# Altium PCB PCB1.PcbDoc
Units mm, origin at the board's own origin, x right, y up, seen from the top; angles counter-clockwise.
Board outline 152.4 x 101.6 mm, 2 copper layers (Top Layer, Bottom Layer); 138 components, 71 nets, 353 pads, 0 vias.
Unrouted connection lines stored in the file: 264.
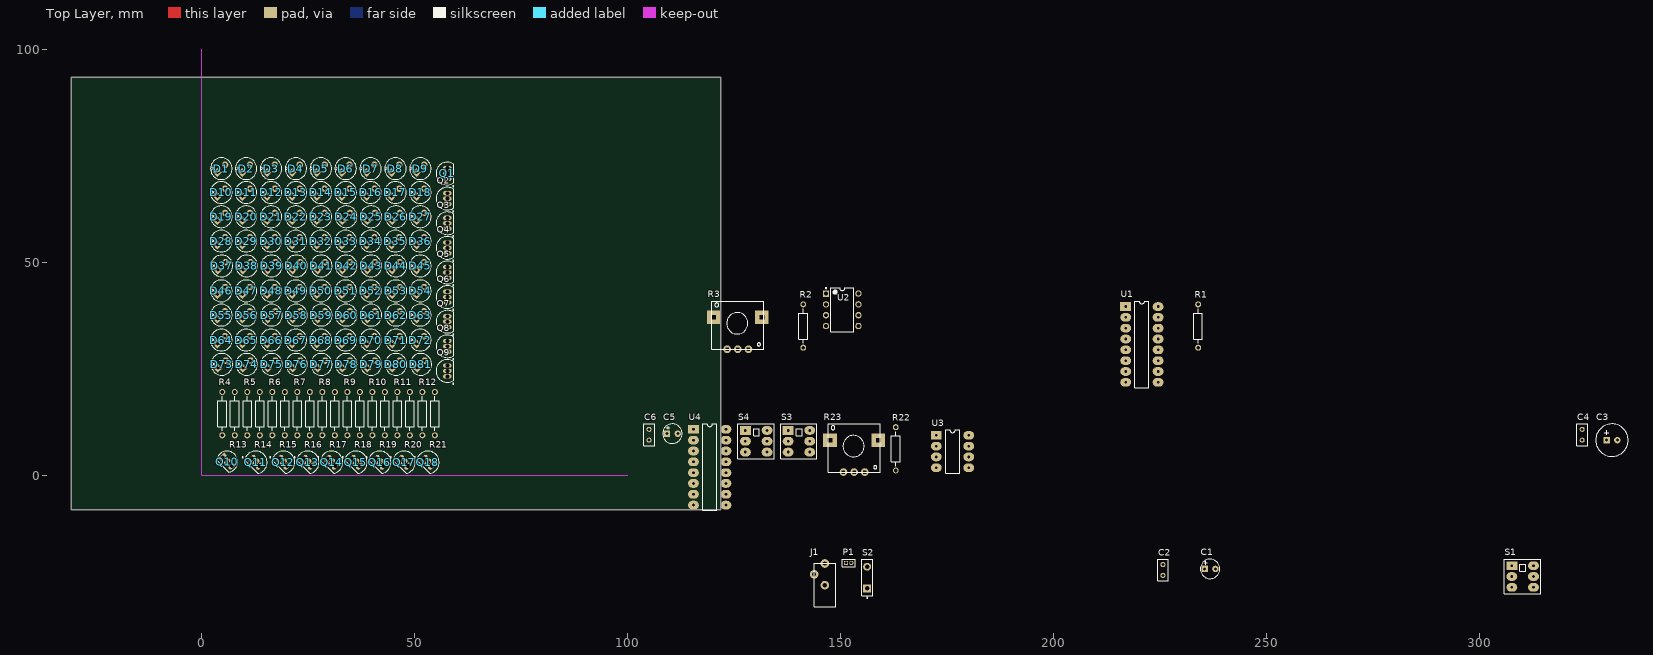
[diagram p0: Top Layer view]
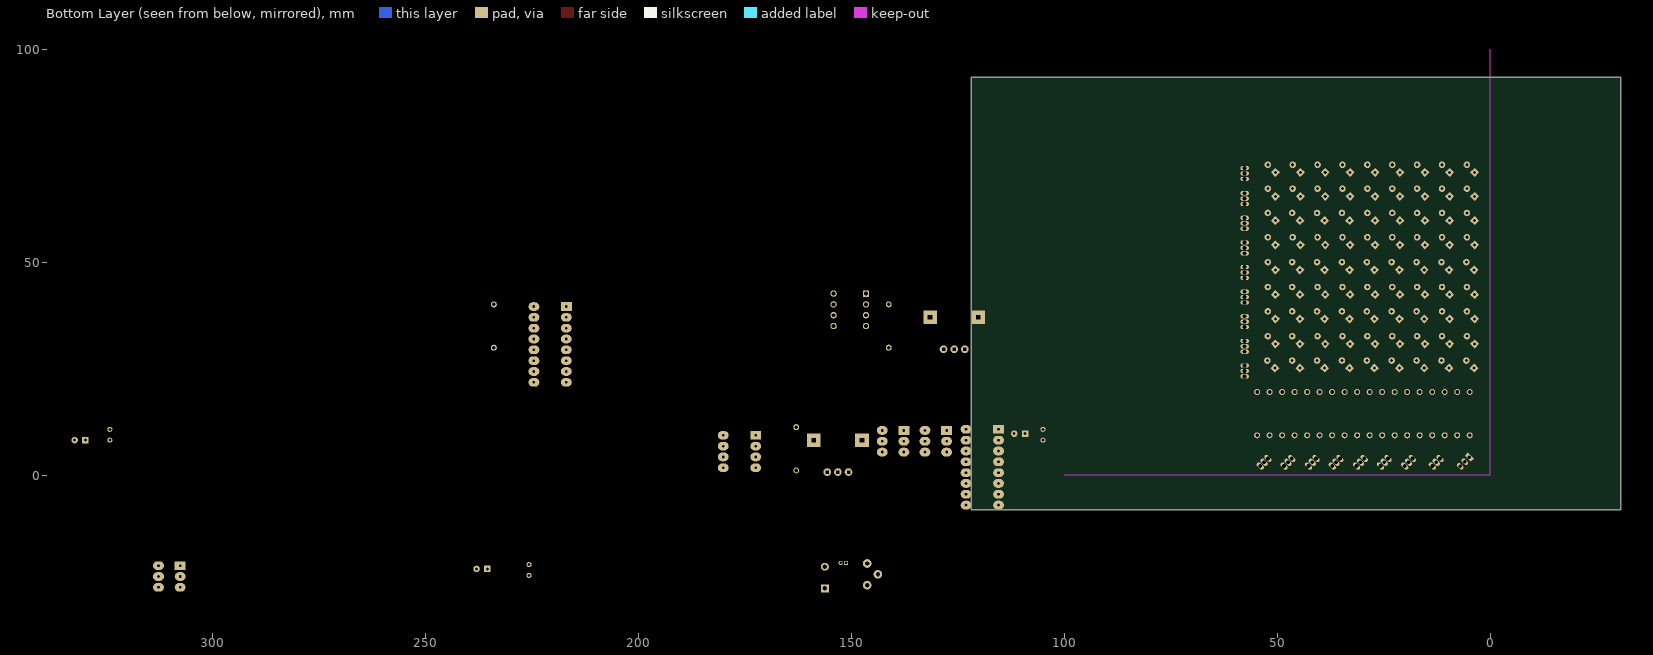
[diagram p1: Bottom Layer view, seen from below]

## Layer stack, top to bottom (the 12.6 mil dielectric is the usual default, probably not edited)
Top Solder: solder mask 0.0102, Solder Resist, Dk 3.5
Top Layer: signal copper 0.0356
Dielectric 1: dielectric 0.32, FR-4, Dk 4.8
Bottom Layer: signal copper 0.0356
Bottom Solder: solder mask 0.0102, Solder Resist, Dk 3.5

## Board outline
-30.607,-8.128 121.793,-8.128 121.793,93.472 -30.607,93.472

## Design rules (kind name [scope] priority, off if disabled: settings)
Clearance [All] p1: gap=0.254
PolygonConnect [All] p1: connectstyle=Relief reliefconductorwidth=0.254 reliefentries=4 polygonreliefangle="90 Angle" airgapwidth=0.254
RoutingVias [All] p1: holewidth=0.711 width=1.27 viastyle="Through Hole" minholewidth=0.711 minwidth=1.27 maxholewidth=0.711 maxwidth=1.27
SolderMaskExpansion [All] p1: expansion=0.102
Width [All] p1: maxlimit=0.254 minlimit=0.254 preferedwidth=0.254
30 further rules are at their usual default settings.

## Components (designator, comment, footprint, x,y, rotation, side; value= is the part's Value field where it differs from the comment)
C1 "Cap Pol2" 1UF电容器 235.458,-21.971 r0 top
C2 "Cap" RAD-0.1 225.679,-22.225 r90 top
C3 "Cap Pol2" 220UF电容 329.819,8.255 r0 top
C4 "Cap" RAD-0.1 324.104,9.525 r90 top
C5 "Cap Pol2" 1UF电容器 109.22,9.779 r0 top
C6 "Cap" RAD-0.1 105.029,9.525 r90 top
D1 "LED1" 发光二极管 3.683,71.12 r45 top
D2 "LED1" 发光二极管 9.525,71.12 r45 top
D3 "LED1" 发光二极管 15.367,71.12 r45 top
D4 "LED1" 发光二极管 21.209,71.12 r45 top
D5 "LED1" 发光二极管 27.051,71.12 r45 top
D6 "LED1" 发光二极管 32.893,71.12 r45 top
D7 "LED1" 发光二极管 38.735,71.12 r45 top
D8 "LED1" 发光二极管 44.577,71.12 r45 top
D9 "LED1" 发光二极管 50.419,71.12 r45 top
D10 "LED1" 发光二极管 3.683,65.514 r45 top
D11 "LED1" 发光二极管 9.525,65.514 r45 top
D12 "LED1" 发光二极管 15.367,65.514 r45 top
D13 "LED1" 发光二极管 21.209,65.514 r45 top
D14 "LED1" 发光二极管 27.051,65.514 r45 top
D15 "LED1" 发光二极管 32.893,65.514 r45 top
D16 "LED1" 发光二极管 38.735,65.514 r45 top
D17 "LED1" 发光二极管 44.577,65.514 r45 top
D18 "LED1" 发光二极管 50.419,65.514 r45 top
D19 "LED1" 发光二极管 3.683,59.817 r45 top
D20 "LED1" 发光二极管 9.525,59.817 r45 top
D21 "LED1" 发光二极管 15.367,59.817 r45 top
D22 "LED1" 发光二极管 21.209,59.817 r45 top
D23 "LED1" 发光二极管 27.051,59.817 r45 top
D24 "LED1" 发光二极管 33.02,59.817 r45 top
D25 "LED1" 发光二极管 38.862,59.817 r45 top
D26 "LED1" 发光二极管 44.704,59.817 r45 top
D27 "LED1" 发光二极管 50.419,59.817 r45 top
D28 "LED1" 发光二极管 3.683,54.102 r45 top
D29 "LED1" 发光二极管 9.525,54.102 r45 top
D30 "LED1" 发光二极管 15.367,54.102 r45 top
D31 "LED1" 发光二极管 21.209,54.102 r45 top
D32 "LED1" 发光二极管 27.051,54.102 r45 top
D33 "LED1" 发光二极管 32.893,54.102 r45 top
D34 "LED1" 发光二极管 38.735,54.102 r45 top
D35 "LED1" 发光二极管 44.577,54.102 r45 top
D36 "LED1" 发光二极管 50.419,54.102 r45 top
D37 "LED1" 发光二极管 3.81,48.26 r45 top
D38 "LED1" 发光二极管 9.652,48.26 r45 top
D39 "LED1" 发光二极管 15.494,48.26 r45 top
D40 "LED1" 发光二极管 21.336,48.26 r45 top
D41 "LED1" 发光二极管 27.178,48.26 r45 top
D42 "LED1" 发光二极管 33.02,48.26 r45 top
D43 "LED1" 发光二极管 38.862,48.26 r45 top
D44 "LED1" 发光二极管 44.704,48.26 r45 top
D45 "LED1" 发光二极管 50.419,48.26 r45 top
D46 "LED1" 发光二极管 3.683,42.418 r45 top
D47 "LED1" 发光二极管 9.525,42.418 r45 top
D48 "LED1" 发光二极管 15.367,42.418 r45 top
D49 "LED1" 发光二极管 21.209,42.418 r45 top
D50 "LED1" 发光二极管 27.051,42.418 r45 top
D51 "LED1" 发光二极管 32.893,42.418 r45 top
D52 "LED1" 发光二极管 38.735,42.418 r45 top
D53 "LED1" 发光二极管 44.704,42.418 r45 top
D54 "LED1" 发光二极管 50.419,42.418 r45 top
D55 "LED1" 发光二极管 3.683,36.703 r45 top
D56 "LED1" 发光二极管 9.525,36.703 r45 top
D57 "LED1" 发光二极管 15.494,36.703 r45 top
D58 "LED1" 发光二极管 21.336,36.703 r45 top
D59 "LED1" 发光二极管 27.178,36.703 r45 top
D60 "LED1" 发光二极管 33.02,36.703 r45 top
D61 "LED1" 发光二极管 38.862,36.703 r45 top
D62 "LED1" 发光二极管 44.704,36.703 r45 top
D63 "LED1" 发光二极管 50.419,36.703 r45 top
D64 "LED1" 发光二极管 3.683,30.861 r45 top
D65 "LED1" 发光二极管 9.525,30.861 r45 top
D66 "LED1" 发光二极管 15.367,30.861 r45 top
D67 "LED1" 发光二极管 21.209,30.861 r45 top
D68 "LED1" 发光二极管 27.051,30.861 r45 top
D69 "LED1" 发光二极管 32.893,30.861 r45 top
D70 "LED1" 发光二极管 38.735,30.861 r45 top
D71 "LED1" 发光二极管 44.704,30.861 r45 top
D72 "LED1" 发光二极管 50.419,30.861 r45 top
D73 "LED1" 发光二极管 3.81,25.146 r45 top
D74 "LED1" 发光二极管 9.652,25.146 r45 top
D75 "LED1" 发光二极管 15.494,25.146 r45 top
D76 "LED1" 发光二极管 21.336,25.146 r45 top
D77 "LED1" 发光二极管 27.178,25.146 r45 top
D78 "LED1" 发光二极管 33.02,25.146 r45 top
D79 "LED1" 发光二极管 38.862,25.146 r45 top
D80 "LED1" 发光二极管 44.704,25.146 r45 top
D81 "LED1" 发光二极管 50.546,25.146 r45 top
J1 "Phonejack2 TN" ? 146.304,-25.781 r90 top
P1 "MHDR1X2" MHDR1X2 151.257,-20.574 r0 top
Q1 "NPN" TO-226-AA 57.658,70.866 r0 top
Q2 "NPN" TO-226-AA 57.658,64.96 r0 top
Q3 "NPN" TO-226-AA 57.658,59.182 r0 top
Q4 "NPN" TO-226-AA 57.658,53.404 r0 top
Q5 "NPN" TO-226-AA 57.658,47.625 r0 top
Q6 "NPN" TO-226-AA 57.658,41.846 r0 top
Q7 "NPN" TO-226-AA 57.658,36.068 r0 top
Q8 "NPN" TO-226-AA 57.658,30.29 r0 top
Q9 "NPN" TO-226-AA 57.658,24.511 r0 top
Q10 "NPN" TO-92-3_L4.9-W3.7-P1.27-L 5.96,3.198 r315 top
Q11 "NPN" TO-226-AA 12.691,3.057 r225 top
Q12 "NPN" TO-226-AA 19.177,3.057 r225 top
Q13 "NPN" TO-226-AA 24.892,3.057 r225 top
Q14 "NPN" TO-226-AA 30.48,3.057 r225 top
Q15 "NPN" TO-226-AA 36.195,3.057 r225 top
Q16 "NPN" TO-226-AA 41.783,3.057 r225 top
Q17 "NPN" TO-226-AA 47.498,3.057 r225 top
Q18 "NPN" TO-226-AA 53.086,3.057 r225 top
R1 "Res2" AXIAL-0.4 233.934,35.052 r90 top
R2 "Res2" AXIAL-0.4 141.224,35.052 r90 top
R3 "RPot" 立式手柄电位器 125.857,29.591 r0 top
R4 "Res2" AXIAL-0.4 4.826,14.478 r90 top
R5 "Res2" AXIAL-0.4 10.698,14.478 r90 top
R6 "Res2" AXIAL-0.4 16.57,14.478 r90 top
R7 "Res2" AXIAL-0.4 22.442,14.478 r90 top
R8 "Res2" AXIAL-0.4 28.314,14.478 r90 top
R9 "Res2" AXIAL-0.4 34.185,14.478 r90 top
R10 "Res2" AXIAL-0.4 40.057,14.478 r90 top
R11 "Res2" AXIAL-0.4 45.929,14.478 r90 top
R12 "Res2" AXIAL-0.4 51.801,14.478 r90 top
R13 "Res2" AXIAL-0.4 7.762,14.478 r90 top
R14 "Res2" AXIAL-0.4 13.634,14.478 r90 top
R15 "Res2" AXIAL-0.4 19.506,14.478 r90 top
R16 "Res2" AXIAL-0.4 25.378,14.478 r90 top
R17 "Res2" AXIAL-0.4 31.249,14.478 r90 top
R18 "Res2" AXIAL-0.4 37.121,14.478 r90 top
R19 "Res2" AXIAL-0.4 42.993,14.478 r90 top
R20 "Res2" AXIAL-0.4 48.865,14.478 r90 top
R21 "Res2" AXIAL-0.4 54.737,14.478 r90 top
R22 "Res2" AXIAL-0.4 162.941,6.223 r90 top
R23 "RPot" 立式手柄电位器 153.162,0.762 r0 top
S1 "SW-SPDT" KEY-6 307.594,-21.209 r0 top
S2 "SW-SPST" SPST-2 156.21,-24.003 r90 top
S3 "SW-SPDT" KEY-6 137.668,10.541 r0 top
S4 "SW-SPDT" KEY-6 127.635,10.541 r0 top
U1 "CD4017BCN" CD4017 216.916,39.624 r0 top
U2 "NE555N" DIP-8 150.368,38.862 r0 top
U3 "NE555N" NE555 172.466,9.398 r0 top
U4 "CD4017BCN" CD4017 115.443,10.795 r0 top

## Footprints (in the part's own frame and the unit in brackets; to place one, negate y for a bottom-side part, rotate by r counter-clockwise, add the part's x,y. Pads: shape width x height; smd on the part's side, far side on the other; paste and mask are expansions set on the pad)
1UF电容器 [mil]
  rect 60x60 hole 28: 1(0,0)
  round 60 hole 28: 2(100,0)
  silkscreen extent -40,-90 140,90
220UF电容 [mil]
  rect 60x60 hole 28: 1(0,0)
  round 60 hole 28: 2(100,0)
  silkscreen extent -100,-150 200,150
AXIAL-0.4 [mm] "Axial Device, Thru-Hole; 2 Leads; 0.4 in Pin Spacing"
  round 1.4 hole 0.85: 1(-5.08,0) 2(5.08,0)
  silkscreen extent -4.06,-1.02 4.06,1.02
CD4017 [mil]
  rect 100x80 hole 25: 1(0,0)
  oval 100x80 hole 25: 2(0,-100) 3(0,-200) 4(0,-300) 5(0,-400) 6(0,-500) 7(0,-600) 8(0,-700) 9(300,-700) 10(300,-600) 11(300,-500) 12(300,-400) 13(300,-300) 14(300,-200) 15(300,-100) 16(300,0)
  silkscreen extent 85,-750 215,50
DIP-8 [mm] "DIP; 8 Leads; Row Spacing 7.62 mm; Pitch 2.54 mm"
  rect 1.5x1.5 hole 0.9: 1(-3.81,3.81)
  round 1.5 hole 0.9: 2(-3.81,1.27) 3(-3.81,-1.27) 4(-3.81,-3.81) 5(3.81,-3.81) 6(3.81,-1.27) 7(3.81,1.27) 8(3.81,3.81)
  silkscreen extent -3.93,-5.15 2.65,5.23, body extent -3.6,-5.15 3.6,5.15, height 5.08
KEY-6 [mil]
  rect 100x80 hole 25: 1(0,0)
  oval 100x80 hole 25: 2(0,-100) 3(0,-200) 4(200,-200) 5(200,-100) 6(200,0)
  silkscreen extent -70,-260 265,60
MHDR1X2 [mm] "Connector; Header; 2 Position"
  rect 1x1 hole 0.6: 1(0,0)
  round 1 hole 0.6: 2(1.27,0)
  silkscreen extent -0.9,-0.9 2.17,0.9
NE555 [mil]
  rect 100x80 hole 25: 1(0,0)
  oval 100x80 hole 25: 2(0,-100) 3(0,-200) 4(0,-300) 5(300,-300) 6(300,-200) 7(300,-100) 8(300,0)
  silkscreen extent 85,-350 215,50
RAD-0.1 [mm] "Radial Cap, Thru-Hole; 2 Leads; 0.1 in Pin Spacing"
  round 1.2 hole 0.7: 1(-1.27,0) 2(1.27,0)
  silkscreen extent -2.54,-1.27 2.54,1.27
SPST-2 [mm] "Switch; 2 Leads"
  rect 1.85x1.85 hole 1.1: 1(-2.54,0)
  round 1.85 hole 1.1: 2(2.54,0)
  silkscreen extent -4.89,-1.27 4.28,1.27
TO-92-3_L4.9-W3.7-P1.27-L [mm]
  rect 1x2 hole 0.8: 1(-1.524,0)
  oval 1x1.8 hole 0.8: 2(0,0) 3(1.524,0)
  silkscreen extent -2.48,-1.5 2.48,2.48
TO-226-AA [mm] "TO, Flat Index; 3 In-Line, Axial Leads; Body Dia. 4.8mm; Leads 0.55 x 0.51 mm (max)"
  oval 2x1 hole 0.9: 1(0,-1.27) 2(0,0) 3(0,1.27)
  silkscreen extent -2.65,-3.13 1.52,2.65, body extent -2.65,-2.66 1.52,2.66, height 5.33
发光二极管 [mil]
  rect 60x60 hole 28: 1(0,0)
  round 60 hole 28: 2(100,0)
  silkscreen extent -50,-100 150,100
立式手柄电位器 [mm]
  round 1.8 hole 0.7 square: 1(-2.5,0) 2(2.5,0) 3(0,0)
  rect 3.2x3.2 hole 1 square: 4(-5.65,7.5) 5(5.65,7.5)
  silkscreen extent -6.1,0 6.1,11.3
? [mil]
  round 80 hole 40: 1(0,0) 2(100,100) 5(200,0)
  silkscreen extent -200,-100 200,100

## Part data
C1 C3 C5: "Polarized Capacitor (Axial)"
C2 C4 C6: "Capacitor"
D1 D2 D3 D4 D5 D6 D7 D8 D9 D10 D11 D12 D13 D14 D15 D16 D17 D18 D19 D20 D21 D22 D23 D24 D25 D26 D27 D28 D29 D30 D31 D32 D33 D34 D35 D36 D37 D38 D39 D40 D41 D42 D43 D44 D45 D46 D47 D48 D49 D50 D51 D52 D53 D54 D55 D56 D57 D58 D59 D60 D61 D62 D63 D64 D65 D66 D67 D68 D69 D70 D71 D72 D73 D74 D75 D76 D77 D78 D79 D80 D81: "Typical RED GaAs LED"
J1: "Jack Socket, 1/4\" [6.5mm], Thru-Hole, Vertical, 2-Conductor with Tip closed"
P1: "Header, 2-Pin"
Q1 Q2 Q3 Q4 Q5 Q6 Q7 Q8 Q9 Q10 Q11 Q12 Q13 Q14 Q15 Q16 Q17 Q18: "NPN Bipolar Transistor"
R1 R2 R4 R5 R6 R7 R8 R9 R10 R11 R12 R13 R14 R15 R16 R17 R18 R19 R20 R21 R22: "Resistor"
R3 R23: "Potentiometer"
S1 S3 S4: "SPDT Subminiature Toggle Switch, Right Angle Mounting, Vertical Actuation"
S2: "Single-Pole, Single-Throw Switch"
U1 U4: "Decade Counter/Divider with 10 Decoded Outputs"
U2 U3: "General-Purpose Single Bipolar Timer"

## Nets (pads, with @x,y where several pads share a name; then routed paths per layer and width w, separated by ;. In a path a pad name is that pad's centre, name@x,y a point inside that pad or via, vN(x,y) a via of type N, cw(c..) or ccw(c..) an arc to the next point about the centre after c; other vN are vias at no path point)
+5V: C3.1 C4.2 Q1.1 Q2.1 Q3.1 Q4.1 Q5.1 Q6.1 Q7.1 Q8.1 Q9.1 R2.1 R22.1 S2.2 U1.16 U2.4 U2.8 U3.4 U3.8 U4.16
GND: C1.2 C2.2 C3.2 C4.1 C5.2 C6.2 J1.5 P1.1 Q10.3 Q11.3 Q12.3 Q13.3 Q14.3 Q15.3 Q16.3 Q17.3 Q18.3 U1.8 U1.13 U2.1 U3.1 U4.8 U4.13
H1: Q1.2 U1.3
H2: Q2.2 U1.2
H3: Q3.2 U1.4
H4: Q4.2 U1.7
H5: Q5.2 U1.10
H6: Q6.2 U1.1
H7: Q7.2 U1.5
H8: Q8.2 U1.6
H9: Q9.2 U1.9
L1: R13.2 U4.3
L2: R14.2 U4.2
L3: R15.2 U4.4
L4: R16.2 U4.7
L5: R17.2 U4.10
L6: R18.2 U4.1
L7: R19.2 U4.5
L8: R20.2 U4.6
L9: R21.2 U4.9
NetC1_1: C1.1 S1.3
NetC2_1: C2.1 S1.1
NetC5_1: C5.1 S4.3
NetC6_1: C6.1 S4.1
NetD1_1: D1.1 D2.1 D3.1 D4.1 D5.1 D6.1 D7.1 D8.1 D9.1 Q1.3
NetD1_2: D1.2 D10.2 D19.2 D28.2 D37.2 D46.2 D55.2 D64.2 D73.2 R4.2
NetD2_2: D2.2 D11.2 D20.2 D29.2 D38.2 D47.2 D56.2 D65.2 D74.2 R5.2
NetD3_2: D3.2 D12.2 D21.2 D30.2 D39.2 D48.2 D57.2 D66.2 D75.2 R6.2
NetD4_2: D4.2 D13.2 D22.2 D31.2 D40.2 D49.2 D58.2 D67.2 D76.2 R7.2
NetD5_2: D5.2 D14.2 D23.2 D32.2 D41.2 D50.2 D59.2 D68.2 D77.2 R8.2
NetD6_2: D6.2 D15.2 D24.2 D33.2 D42.2 D51.2 D60.2 D69.2 D78.2 R9.2
NetD7_2: D7.2 D16.2 D25.2 D34.2 D43.2 D52.2 D61.2 D70.2 D79.2 R10.2
NetD8_2: D8.2 D17.2 D26.2 D35.2 D44.2 D53.2 D62.2 D71.2 D80.2 R11.2
NetD9_2: D9.2 D18.2 D27.2 D36.2 D45.2 D54.2 D63.2 D72.2 D81.2 R12.2
NetD10_1: D10.1 D11.1 D12.1 D13.1 D14.1 D15.1 D16.1 D17.1 D18.1 Q2.3
NetD19_1: D19.1 D20.1 D21.1 D22.1 D23.1 D24.1 D25.1 D26.1 D27.1 Q3.3
NetD28_1: D28.1 D29.1 D30.1 D31.1 D32.1 D33.1 D34.1 D35.1 D36.1 Q4.3
NetD37_1: D37.1 D38.1 D39.1 D40.1 D41.1 D42.1 D43.1 D44.1 D45.1 Q5.3
NetD46_1: D46.1 D47.1 D48.1 D49.1 D50.1 D51.1 D52.1 D53.1 D54.1 Q6.3
NetD55_1: D55.1 D56.1 D57.1 D58.1 D59.1 D60.1 D61.1 D62.1 D63.1 Q7.3
NetD64_1: D64.1 D65.1 D66.1 D67.1 D68.1 D69.1 D70.1 D71.1 D72.1 Q8.3
NetD73_1: D73.1 D74.1 D75.1 D76.1 D77.1 D78.1 D79.1 D80.1 D81.1 Q9.3
NetJ1_1: J1.1 P1.2 S2.1
NetQ10_1: Q10.1 R4.1
NetQ10_2: Q10.2 R13.1
NetQ11_1: Q11.1 R5.1
NetQ11_2: Q11.2 R14.1
NetQ12_1: Q12.1 R6.1
NetQ12_2: Q12.2 R15.1
NetQ13_1: Q13.1 R7.1
NetQ13_2: Q13.2 R16.1
NetQ14_1: Q14.1 R8.1
NetQ14_2: Q14.2 R17.1
NetQ15_1: Q15.1 R9.1
NetQ15_2: Q15.2 R18.1
NetQ16_1: Q16.1 R10.1
NetQ16_2: Q16.2 R19.1
NetQ17_1: Q17.1 R11.1
NetQ17_2: Q17.2 R20.1
NetQ18_1: Q18.1 R12.1
NetQ18_2: Q18.2 R21.1
NetR1_1: R1.1 U1.15
NetR1_2: R1.2 S3.1 U1.11
NetR2_2: R2.2 R3.2 R3.3 U2.7
NetR3_1: R3.1 S1.2 U2.2 U2.6
NetR22_2: R22.2 R23.2 R23.3 U3.7
NetR23_1: R23.1 S4.2 U3.2 U3.6
NetS3_2: S3.2 U4.14
NetS3_3: S3.3 U3.3
NetU1_14: U1.14 U2.3
NetU4_11: U4.11 U4.15
pads on no net: J1.2 R3.4 R3.5 R23.4 R23.5 S1.4 S1.5 S1.6 S3.4 S3.5 S3.6 S4.4 S4.5 S4.6 U1.12 U2.5 U3.5 U4.12

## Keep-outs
Keep-Out Layer:
  lines w0.254: 0,100 0,0 100,0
